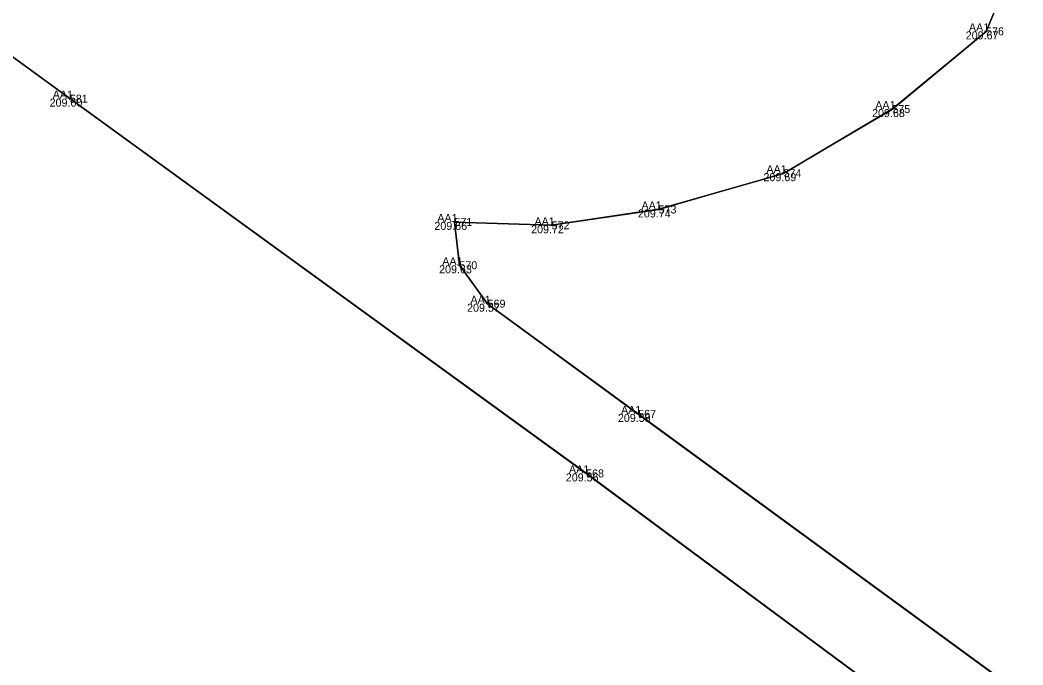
# Model space of a CAD drawing. Extents: x -263091 to -262565, y -1238731 to -1237092.
# Drawn here: x -262955.92 to -262930.86, y -1238410.57 to -1238394.45 of the extents above; entities that cross this region are included whole.
import ezdxf

# ---------------------------------------------------------------- set-up
doc = ezdxf.new("R2010")
doc.units = 0
for name, color, linetype in [('03_Asfalt', 7, 'Continuous'), ('10', 7, 'Continuous'), ('Groma (21)', 7, 'Continuous'), ('Groma (22)', 7, 'Continuous'), ('Groma (23)', 7, 'Continuous'), ('Groma (24)', 7, 'Continuous'), ('U001_Zeleň_mimo', 7, 'Continuous'), ('U002_Asfalt', 7, 'Continuous'), ('U002_Zeleň_mimo', 7, 'Continuous')]:
    doc.layers.add(name, color=color, linetype=linetype)

msp = doc.modelspace()

# ---------------------------------------------------------------- linework, layer by layer
at = {"layer": '03_Asfalt'}
for points in [[(-262913.444, -1238391.676), (-262911.985, -1238397.337), (-262910.006, -1238403.107), (-262907.769, -1238409.039), (-262901.709, -1238424.56), (-262896.942, -1238436.871), (-262897.547, -1238437.016), (-262898.706, -1238436.381), (-262904.848, -1238431.522), (-262916.36, -1238422.355), (-262927.608, -1238413.712), (-262940.472, -1238404.296), (-262944.235, -1238401.54), (-262944.94, -1238400.579), (-262945.063, -1238399.495), (-262942.635, -1238399.58), (-262939.962, -1238399.183), (-262936.84, -1238398.276), (-262934.121, -1238396.673), (-262931.78, -1238394.73), (-262927.567, -1238384.599)], [(-262804.465, -1238690.033), (-262818.631, -1238655.736), (-262826.695, -1238636.389), (-262836.855, -1238611.872), (-262842.406, -1238598.306), (-262850.452, -1238578.707), (-262858.82, -1238561.234), (-262870.509, -1238539), (-262873.344, -1238533.53), (-262876.375, -1238529.239), (-262880.031, -1238521.826), (-262869.115, -1238517.45), (-262870.175, -1238508.052), (-262871.319, -1238501.744), (-262886.895, -1238462.375), (-262895.067, -1238441.663), (-262905.824, -1238433.621), (-262917.716, -1238423.993), (-262928.896, -1238415.327), (-262941.774, -1238405.784), (-262954.673, -1238396.412), (-262962.054, -1238391.026)]]:
    msp.add_lwpolyline(points, dxfattribs=at)
at = {"layer": '10'}
msp.add_lwpolyline([(-262982.434, -1238375.977), (-262968.907, -1238386.238), (-262962.054, -1238391.026), (-262954.673, -1238396.412), (-262941.774, -1238405.784), (-262928.896, -1238415.327), (-262917.716, -1238423.993), (-262905.824, -1238433.621), (-262895.067, -1238441.663), (-262870.407, -1238460.6)], dxfattribs=at)
at = {"layer": 'Groma (21)'}
for centre in [(-262931.78, -1238394.73), (-262954.673, -1238396.412), (-262934.121, -1238396.673), (-262936.84, -1238398.276), (-262939.962, -1238399.183), (-262945.063, -1238399.495), (-262942.635, -1238399.58), (-262944.94, -1238400.579), (-262944.235, -1238401.54), (-262940.472, -1238404.296), (-262941.774, -1238405.784)]:
    msp.add_circle(centre, 0.01, dxfattribs=at)
at = {"layer": 'U001_Zeleň_mimo'}
msp.add_lwpolyline([(-262962.05, -1238391.03), (-262954.67, -1238396.41), (-262941.77, -1238405.78), (-262928.9, -1238415.33), (-262917.72, -1238423.99), (-262905.82, -1238433.62), (-262895.07, -1238441.66), (-262886.9, -1238462.38), (-262871.32, -1238501.74), (-262870.18, -1238508.05), (-262869.12, -1238517.45), (-262880.03, -1238521.83), (-262876.38, -1238529.24), (-262873.34, -1238533.53), (-262870.51, -1238539), (-262858.82, -1238561.23), (-262850.45, -1238578.71), (-262842.41, -1238598.31), (-262836.86, -1238611.87), (-262826.7, -1238636.39), (-262818.63, -1238655.74), (-262804.47, -1238690.03)], dxfattribs=at)
at = {"layer": 'U002_Asfalt'}
for points in [[(-262927.57, -1238384.6), (-262931.78, -1238394.73), (-262934.12, -1238396.67), (-262936.84, -1238398.28), (-262939.96, -1238399.18), (-262942.64, -1238399.58), (-262945.06, -1238399.5), (-262944.94, -1238400.58), (-262944.24, -1238401.54), (-262940.47, -1238404.3), (-262927.61, -1238413.71), (-262916.36, -1238422.36), (-262904.85, -1238431.52), (-262898.71, -1238436.38), (-262897.55, -1238437.02), (-262896.94, -1238436.87), (-262895.07, -1238441.66), (-262905.82, -1238433.62), (-262917.72, -1238423.99), (-262928.9, -1238415.33), (-262941.77, -1238405.78), (-262954.67, -1238396.41), (-262962.05, -1238391.03)], [(-262927.57, -1238384.6), (-262931.78, -1238394.73), (-262934.12, -1238396.67), (-262936.84, -1238398.28), (-262939.96, -1238399.18), (-262942.64, -1238399.58), (-262945.06, -1238399.5), (-262944.94, -1238400.58), (-262944.24, -1238401.54), (-262940.47, -1238404.3), (-262927.61, -1238413.71), (-262916.36, -1238422.36), (-262904.85, -1238431.52), (-262898.71, -1238436.38), (-262897.55, -1238437.02), (-262896.94, -1238436.87), (-262895.07, -1238441.66)], [(-262895.07, -1238441.66), (-262905.82, -1238433.62), (-262917.72, -1238423.99), (-262928.9, -1238415.33), (-262941.77, -1238405.78), (-262954.67, -1238396.41), (-262962.05, -1238391.03)]]:
    msp.add_lwpolyline(points, dxfattribs=at)
at = {"layer": 'U002_Zeleň_mimo'}
msp.add_lwpolyline([(-262913.44, -1238391.68), (-262911.99, -1238397.34), (-262910.01, -1238403.11), (-262907.77, -1238409.04), (-262901.71, -1238424.56), (-262896.94, -1238436.87), (-262897.55, -1238437.02), (-262898.71, -1238436.38), (-262904.85, -1238431.52), (-262916.36, -1238422.36), (-262927.61, -1238413.71), (-262940.47, -1238404.3), (-262944.24, -1238401.54), (-262944.94, -1238400.58), (-262945.06, -1238399.5), (-262942.64, -1238399.58), (-262939.96, -1238399.18), (-262936.84, -1238398.28), (-262934.12, -1238396.67), (-262931.78, -1238394.73), (-262927.57, -1238384.6)], dxfattribs=at)

# ---------------------------------------------------------------- texts
at = {"layer": 'Groma (22)'}
for s, p in [('576', (-262931.78, -1238394.83)), ('581', (-262954.673, -1238396.512)), ('575', (-262934.121, -1238396.773)), ('574', (-262936.84, -1238398.376)), ('573', (-262939.962, -1238399.283)), ('571', (-262945.063, -1238399.595)), ('572', (-262942.635, -1238399.68)), ('570', (-262944.94, -1238400.679)), ('569', (-262944.235, -1238401.64)), ('567', (-262940.472, -1238404.396)), ('568', (-262941.774, -1238405.884))]:
    msp.add_text(s, height=0.2, dxfattribs=at).set_placement(p)
at = {"layer": 'Groma (23)'}
for s, p in [('209.67', (-262932.288, -1238394.93)), ('209.60', (-262955.179, -1238396.612)), ('209.68', (-262934.628, -1238396.873)), ('209.69', (-262937.342, -1238398.476)), ('209.74', (-262940.479, -1238399.383)), ('209.66', (-262945.565, -1238399.695)), ('209.72', (-262943.148, -1238399.78)), ('209.63', (-262945.447, -1238400.779)), ('209.57', (-262944.748, -1238401.74)), ('209.59', (-262940.979, -1238404.496)), ('209.56', (-262942.281, -1238405.984))]:
    msp.add_text(s, height=0.2, dxfattribs=at).set_placement(p)
at = {"layer": 'Groma (24)'}
for p in [(-262932.208, -1238394.73), (-262955.101, -1238396.412), (-262934.549, -1238396.673), (-262937.268, -1238398.276), (-262940.39, -1238399.183), (-262945.491, -1238399.495), (-262943.063, -1238399.58), (-262945.368, -1238400.579), (-262944.663, -1238401.54), (-262940.9, -1238404.296), (-262942.202, -1238405.784)]:
    msp.add_text('AA1', height=0.2, dxfattribs=at).set_placement(p)

doc.saveas('drawing.dxf')
